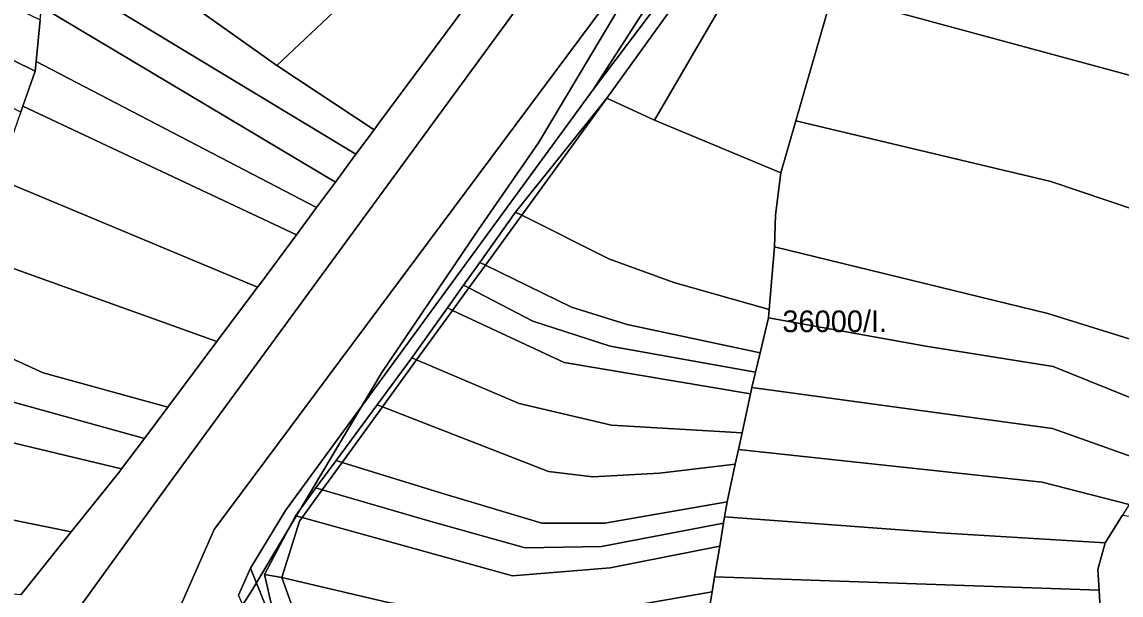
# Model space of a CAD drawing. Extents: x -537068 to -534056, y -1176840 to -1172401.
# Drawn here: x -535764.1 to -535510.5, y -1176353.3 to -1176221.1 of the extents above; entities that cross this region are included whole.
import ezdxf

# ---------------------------------------------------------------- set-up
doc = ezdxf.new("R2010")
doc.units = 0
for name, color, linetype in [('95560013', 7, 'Continuous'), ('95600013', 7, 'Continuous'), ('95610013', 7, 'Continuous'), ('95630013', 7, 'Continuous'), ('95640013', 7, 'Continuous'), ('95660013', 7, 'Continuous')]:
    doc.layers.add(name, color=color, linetype=linetype)

msp = doc.modelspace()

# ---------------------------------------------------------------- linework, layer by layer
at = {"layer": '95560013'}
for points in [[(-535612.96, -1176137.93), (-535644.01, -1176170.85), (-535663.42, -1176191.77), (-535705.22, -1176231.15), (-535722.18, -1176219.19), (-535709.29, -1176207.51), (-535686.2, -1176185.54), (-535651.4, -1176150.28), (-535640.87, -1176138.09), (-535597.55, -1176091.6), (-535584.85, -1176104.39), (-535582.44, -1176105.37)], [(-535681.71, -1176244.51), (-535682.81, -1176246), (-535705.22, -1176231.15), (-535663.42, -1176191.77), (-535644.01, -1176170.85), (-535612.96, -1176137.93), (-535582.44, -1176105.37), (-535579.75, -1176106.46), (-535626.09, -1176169.01), (-535657.63, -1176212.04)], [(-535819.05, -1176203.85), (-535893.77, -1176166.47), (-535967.89, -1176126.99), (-535958.85, -1176118.83), (-535920.11, -1176140.39), (-535872.12, -1176165.77), (-535818.2, -1176192.48), (-535759.88, -1176220.62), (-535760.8, -1176230.25), (-535761.01, -1176232.45)], [(-535819.05, -1176203.85), (-535761.01, -1176232.45), (-535763.83, -1176240.59), (-535764.29, -1176241.92), (-535820.68, -1176214.13), (-535866.12, -1176192.08), (-535896.58, -1176176.76), (-535975.82, -1176134.14), (-535967.89, -1176126.99), (-535893.77, -1176166.47)], [(-535730.13, -1176213.52), (-535722.18, -1176219.19), (-535705.22, -1176231.15), (-535682.81, -1176246), (-535686.99, -1176251.65), (-535757.36, -1176209.08), (-535756.5, -1176205.81), (-535760.04, -1176204.48), (-535752.93, -1176197.27), (-535744.73, -1176203.12), (-535737.35, -1176208.38)], [(-535757.36, -1176209.08), (-535686.99, -1176251.65), (-535691.75, -1176258.07), (-535759.59, -1176217.62)], [(-535696.1, -1176263.94), (-535760.8, -1176230.25), (-535759.88, -1176220.62), (-535759.59, -1176217.62), (-535691.75, -1176258.07)], [(-535696.1, -1176263.94), (-535700.74, -1176270.21), (-535763.83, -1176240.59), (-535761.01, -1176232.45), (-535760.8, -1176230.25)], [(-535700.74, -1176270.21), (-535709.27, -1176281.73), (-535709.73, -1176282.34), (-535769, -1176257.52), (-535767.85, -1176252.17), (-535764.29, -1176241.92), (-535763.83, -1176240.59)], [(-535770.08, -1176262.56), (-535769, -1176257.52), (-535709.73, -1176282.34), (-535719.11, -1176294.83), (-535773.43, -1176275.36), (-535772.25, -1176272.65)], [(-535730.4, -1176309.95), (-535759.14, -1176302.07), (-535779.59, -1176292.76), (-535778.71, -1176289.95), (-535775.91, -1176281.02), (-535773.43, -1176275.36), (-535719.11, -1176294.83)], [(-535735.81, -1176317.18), (-535765.44, -1176308.99), (-535782.75, -1176302.84), (-535781.56, -1176299.03), (-535779.59, -1176292.76), (-535759.14, -1176302.07), (-535730.4, -1176309.95)], [(-535782.75, -1176302.84), (-535765.44, -1176308.99), (-535735.81, -1176317.18), (-535741.07, -1176324.23), (-535786.07, -1176313.43), (-535784.17, -1176307.37)], [(-535786.51, -1176314.83), (-535786.07, -1176313.43), (-535741.07, -1176324.23), (-535741.6, -1176324.94), (-535752.68, -1176338.75), (-535767.46, -1176335.71), (-535791.36, -1176330.33), (-535788.97, -1176322.69)], [(-535793.97, -1176340.35), (-535791.7, -1176331.64), (-535791.36, -1176330.33), (-535767.46, -1176335.71), (-535752.68, -1176338.75), (-535764.34, -1176353.29), (-535777, -1176352.17), (-535795.64, -1176346.74)], [(-535604.24, -1176349.09), (-535603.06, -1176342.03), (-535602.18, -1176336.77), (-535601.93, -1176335.24), (-535552.2, -1176338.93), (-535514.1, -1176341.26), (-535515.82, -1176347.42), (-535515.55, -1176352.17)]]:
    msp.add_lwpolyline(points, close=True, dxfattribs=at)
at = {"layer": '95600013'}
for points in [[(-535572, -1176216.24), (-535561.73, -1176189.89), (-535455.77, -1176220.54), (-535454.33, -1176224.52), (-535453.34, -1176227.24), (-535446.15, -1176234.72), (-535442.76, -1176242.32), (-535443.24, -1176247.61), (-535444.07, -1176250.24), (-535447.33, -1176253.67), (-535450.43, -1176256.92), (-535476.72, -1176242.86), (-535504.91, -1176234.39)], [(-535601.8, -1176203.42), (-535596.23, -1176206.1), (-535618.12, -1176243.8), (-535629.13, -1176238.73), (-535604.01, -1176203.9)], [(-535596.23, -1176206.1), (-535578.48, -1176214.72), (-535577.58, -1176216.53), (-535585.5, -1176243.95), (-535588.97, -1176255.95), (-535618.12, -1176243.8)], [(-535468.52, -1176271.99), (-535473.99, -1176275.67), (-535526.7, -1176257.92), (-535585.5, -1176243.95), (-535577.58, -1176216.53), (-535576.27, -1176219.16), (-535572, -1176216.24), (-535504.91, -1176234.39), (-535476.72, -1176242.86), (-535450.43, -1176256.92), (-535453.28, -1176259.65), (-535460.58, -1176266.64)], [(-535613.65, -1176281.22), (-535628.68, -1176275.75), (-535648.75, -1176265.71), (-535629.13, -1176238.73), (-535618.12, -1176243.8), (-535588.97, -1176255.95), (-535590.2, -1176265.71), (-535590.4, -1176273), (-535591.62, -1176287.49)], [(-535527.32, -1176288.35), (-535590.4, -1176273), (-535590.2, -1176265.71), (-535588.97, -1176255.95), (-535585.5, -1176243.95), (-535526.7, -1176257.92), (-535473.99, -1176275.67), (-535476.97, -1176280.63), (-535482.14, -1176289.27), (-535488.81, -1176300.39)], [(-535591.62, -1176287.49), (-535591.78, -1176289.34), (-535593.72, -1176297.46), (-535624.44, -1176290.95), (-535637.25, -1176286.95), (-535657.12, -1176277.22), (-535648.75, -1176265.71), (-535628.68, -1176275.75), (-535613.65, -1176281.22)], [(-535591.78, -1176289.34), (-535591.62, -1176287.49), (-535590.4, -1176273), (-535527.32, -1176288.35), (-535488.81, -1176300.39), (-535492.21, -1176306.06), (-535496.17, -1176312.67), (-535526.15, -1176300.62), (-535555.51, -1176295.95)], [(-535628.33, -1176295.89), (-535646.18, -1176290.17), (-535660.94, -1176282.47), (-535657.12, -1176277.22), (-535637.25, -1176286.95), (-535624.44, -1176290.95), (-535593.72, -1176297.46), (-535594.79, -1176301.93)], [(-535628.33, -1176295.89), (-535594.79, -1176301.93), (-535595.64, -1176305.46), (-535595.96, -1176306.93), (-535638.95, -1176299.71), (-535664.71, -1176287.65), (-535660.94, -1176282.47), (-535646.18, -1176290.17)], [(-535597.9, -1176315.87), (-535628.05, -1176314.15), (-535649.33, -1176309.15), (-535673.01, -1176299.08), (-535664.71, -1176287.65), (-535638.95, -1176299.71), (-535595.96, -1176306.93)], [(-535591.78, -1176289.34), (-535555.51, -1176295.95), (-535526.15, -1176300.62), (-535496.17, -1176312.67), (-535497.01, -1176313.83), (-535503.58, -1176322.96), (-535526.27, -1176314.9), (-535595.64, -1176305.46), (-535594.79, -1176301.93), (-535593.72, -1176297.46)], [(-535598.74, -1176319.75), (-535599.48, -1176323.15), (-535616.96, -1176325.22), (-535632.32, -1176326.02), (-535642.6, -1176324.8), (-535680.9, -1176309.93), (-535673.01, -1176299.08), (-535649.33, -1176309.15), (-535628.05, -1176314.15), (-535597.9, -1176315.87)], [(-535595.96, -1176306.93), (-535595.64, -1176305.46), (-535526.27, -1176314.9), (-535503.58, -1176322.96), (-535506.75, -1176329.57), (-535508.56, -1176332.43), (-535528.69, -1176327.28), (-535598.74, -1176319.75), (-535597.9, -1176315.87)], [(-535599.48, -1176323.15), (-535601.36, -1176331.84), (-535629.56, -1176336.75), (-535644.09, -1176336.75), (-535667.46, -1176329.72), (-535690.21, -1176322.74), (-535680.9, -1176309.93), (-535642.6, -1176324.8), (-535632.32, -1176326.02), (-535616.96, -1176325.22)], [(-535510.12, -1176334.91), (-535514.1, -1176341.26), (-535552.2, -1176338.93), (-535601.93, -1176335.24), (-535601.36, -1176331.84), (-535599.48, -1176323.15), (-535598.74, -1176319.75), (-535528.69, -1176327.28), (-535508.56, -1176332.43)], [(-535602.18, -1176336.77), (-535630.32, -1176342.1), (-535647.92, -1176342.41), (-535669.93, -1176336.25), (-535694.79, -1176329.04), (-535690.21, -1176322.74), (-535667.46, -1176329.72), (-535644.09, -1176336.75), (-535629.56, -1176336.75), (-535601.36, -1176331.84), (-535601.93, -1176335.24)], [(-535647.92, -1176342.41), (-535630.32, -1176342.1), (-535602.18, -1176336.77), (-535603.06, -1176342.03), (-535628.31, -1176347.04), (-535650.9, -1176348.88), (-535699.43, -1176335.44), (-535694.79, -1176329.04), (-535669.93, -1176336.25)], [(-535628.31, -1176347.04), (-535603.06, -1176342.03), (-535604.24, -1176349.09), (-535604.83, -1176352.6), (-535646.71, -1176359.86), (-535661.64, -1176358.21), (-535679.91, -1176354.99), (-535704.11, -1176349.3), (-535700.03, -1176336.26), (-535699.43, -1176335.44), (-535650.9, -1176348.88)], [(-535506.9, -1176370.34), (-535512.14, -1176372.81), (-535514.88, -1176363.66), (-535515.55, -1176352.17), (-535515.82, -1176347.42), (-535514.1, -1176341.26), (-535510.12, -1176334.91), (-535503.05, -1176335.99), (-535508.5, -1176350.52), (-535506.93, -1176365.74), (-535501.24, -1176369.64)], [(-535704.11, -1176349.3), (-535679.91, -1176354.99), (-535661.64, -1176358.21), (-535646.71, -1176359.86), (-535604.83, -1176352.6), (-535606.33, -1176361.55), (-535634.31, -1176368.39), (-535649.89, -1176369.93), (-535660.92, -1176370.49), (-535671.99, -1176369.97), (-535687.44, -1176367.24), (-535698.43, -1176365.11)], [(-535514.88, -1176363.66), (-535553.78, -1176364.17), (-535606.7, -1176363.78), (-535606.33, -1176361.55), (-535604.83, -1176352.6), (-535604.24, -1176349.09), (-535515.55, -1176352.17)]]:
    msp.add_lwpolyline(points, close=True, dxfattribs=at)
at = {"layer": '95610013'}
msp.add_lwpolyline([(-535704.53, -1176363.92), (-535708.02, -1176366.7), (-535709.93, -1176362.48), (-535714.08, -1176353.32), (-535711.31, -1176347.15)], close=True, dxfattribs=at)
at = {"layer": '95630013'}
for points in [[(-535770.56, -1176383.3), (-535730.11, -1176327.61), (-535618.7, -1176175.44), (-535573.32, -1176114.34), (-535569.67, -1176112.77), (-535564.37, -1176109.77), (-535563.79, -1176109), (-535561.44, -1176105.86), (-535560.85, -1176105.07), (-535559.72, -1176099.15), (-535558.92, -1176094.95), (-535542.52, -1176072.87), (-535453.51, -1175948.22)], [(-535441.16, -1175960.3), (-535533.07, -1176086.26), (-535552.34, -1176112.51), (-535554.69, -1176115.71), (-535606.4, -1176186.14), (-535719.7, -1176338.16), (-535728.45, -1176358.09)]]:
    msp.add_lwpolyline(points, dxfattribs=at)
at = {"layer": '95640013'}
for points in [[(-535453.51, -1175948.22), (-535542.52, -1176072.87), (-535558.92, -1176094.95), (-535559.72, -1176099.15), (-535560.85, -1176105.07), (-535561.44, -1176105.86), (-535563.79, -1176109), (-535564.37, -1176109.77), (-535569.67, -1176112.77), (-535573.32, -1176114.34), (-535618.7, -1176175.44), (-535730.11, -1176327.61), (-535770.56, -1176383.3)], [(-535728.45, -1176358.09), (-535719.7, -1176338.16), (-535606.4, -1176186.14), (-535554.69, -1176115.71), (-535552.34, -1176112.51), (-535533.07, -1176086.26), (-535441.16, -1175960.3)], [(-535455.23, -1175987.51), (-535530.06, -1176090.53), (-535532.28, -1176105.42), (-535540.24, -1176112.01), (-535545.43, -1176110.93), (-535546.85, -1176113.06), (-535551.69, -1176120.31), (-535553.82, -1176123.5), (-535550.75, -1176127.07), (-535552.89, -1176133.89), (-535570.8, -1176146.67), (-535602.1, -1176189.88), (-535632.19, -1176236.64), (-535703.24, -1176333.84), (-535711.31, -1176347.15), (-535714.08, -1176353.32)], [(-535604.01, -1176203.9), (-535629.13, -1176238.73), (-535650.19, -1176264.99), (-535658.43, -1176276.58), (-535662.17, -1176281.83), (-535665.91, -1176287.09), (-535674.11, -1176298.61), (-535682.11, -1176309.46), (-535691.59, -1176322.32), (-535696.24, -1176328.62), (-535700.95, -1176335.02), (-535708.09, -1176348.57), (-535704.53, -1176363.92), (-535711.31, -1176347.15), (-535703.24, -1176333.84), (-535632.19, -1176236.64), (-535604.37, -1176199.71)], [(-535764.34, -1176353.29), (-535752.68, -1176338.75), (-535741.6, -1176324.94), (-535741.07, -1176324.23), (-535735.81, -1176317.18), (-535730.4, -1176309.95), (-535719.11, -1176294.83), (-535709.73, -1176282.34), (-535709.27, -1176281.73), (-535700.74, -1176270.21), (-535696.1, -1176263.94), (-535691.75, -1176258.07), (-535686.99, -1176251.65), (-535682.81, -1176246), (-535681.71, -1176244.51), (-535657.63, -1176212.04)]]:
    msp.add_lwpolyline(points, dxfattribs=at)
for points in [[(-535604.37, -1176199.71), (-535632.19, -1176236.64), (-535602.1, -1176189.88)], [(-535648.75, -1176265.71), (-535650.19, -1176264.99), (-535629.13, -1176238.73)], [(-535657.12, -1176277.22), (-535658.43, -1176276.58), (-535650.19, -1176264.99), (-535648.75, -1176265.71)], [(-535662.17, -1176281.83), (-535658.43, -1176276.58), (-535657.12, -1176277.22), (-535660.94, -1176282.47)], [(-535662.17, -1176281.83), (-535660.94, -1176282.47), (-535664.71, -1176287.65), (-535665.91, -1176287.09)], [(-535673.01, -1176299.08), (-535674.11, -1176298.61), (-535665.91, -1176287.09), (-535664.71, -1176287.65)], [(-535682.11, -1176309.46), (-535674.11, -1176298.61), (-535673.01, -1176299.08), (-535680.9, -1176309.93)], [(-535690.21, -1176322.74), (-535691.59, -1176322.32), (-535682.11, -1176309.46), (-535680.9, -1176309.93)], [(-535690.21, -1176322.74), (-535694.79, -1176329.04), (-535696.24, -1176328.62), (-535691.59, -1176322.32)], [(-535696.24, -1176328.62), (-535694.79, -1176329.04), (-535699.43, -1176335.44), (-535700.95, -1176335.02)], [(-535704.11, -1176349.3), (-535708.09, -1176348.57), (-535700.95, -1176335.02), (-535699.43, -1176335.44), (-535700.03, -1176336.26)], [(-535708.09, -1176348.57), (-535704.11, -1176349.3), (-535698.43, -1176365.11), (-535704.53, -1176363.92)]]:
    msp.add_lwpolyline(points, close=True, dxfattribs=at)
at = {"layer": '95660013'}
for points in [[(-535730.62, -1176383), (-535710.87, -1176352), (-535681, -1176302), (-535658.69, -1176269), (-535644.87, -1176249), (-535612.69, -1176195), (-535593.87, -1176169), (-535582.37, -1176152), (-535574.81, -1176142), (-535540.87, -1176093), (-535519.37, -1176067), (-535481, -1176019)], [(-535481, -1176019), (-535519.37, -1176067), (-535540.87, -1176093), (-535574.81, -1176142), (-535582.37, -1176152), (-535593.87, -1176169), (-535612.69, -1176195), (-535644.87, -1176249), (-535658.69, -1176269), (-535681, -1176302), (-535710.87, -1176352), (-535730.62, -1176383)]]:
    msp.add_lwpolyline(points, dxfattribs=at)

# ---------------------------------------------------------------- texts
msp.add_text('36000/I.', height=5, rotation=360, dxfattribs=at).set_placement((-535588.61, -1176292.68))

doc.saveas('drawing.dxf')
